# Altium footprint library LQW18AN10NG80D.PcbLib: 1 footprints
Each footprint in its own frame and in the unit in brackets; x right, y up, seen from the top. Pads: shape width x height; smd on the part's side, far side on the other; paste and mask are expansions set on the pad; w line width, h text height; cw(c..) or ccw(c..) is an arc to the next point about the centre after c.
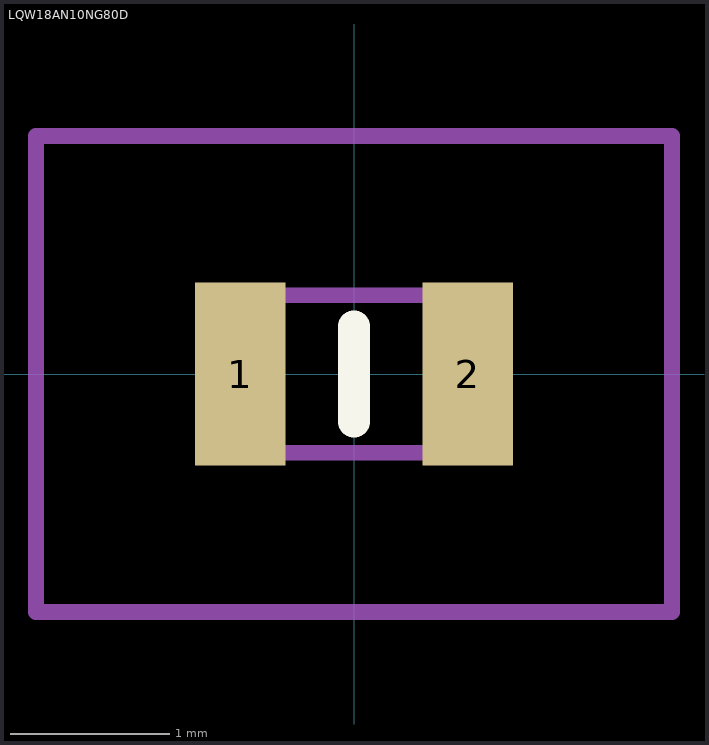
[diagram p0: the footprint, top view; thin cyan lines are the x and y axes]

## LQW18AN10NG80D [mm]
pads (2):
  rect 0.57x1.15 smd: 1(-0.715,0) 2(0.715,0)
Top Overlay:
  lines w0.2: 0,-0.3 0,0.3
Mechanical 15:
  lines w0.1: -0.825,-0.495 0.825,-0.495 0.825,0.495 -0.825,0.495 -0.825,-0.495
Mechanical 20:
  lines w0.1: -2,-1.495 2,-1.495 2,1.495 -2,1.495 -2,-1.495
